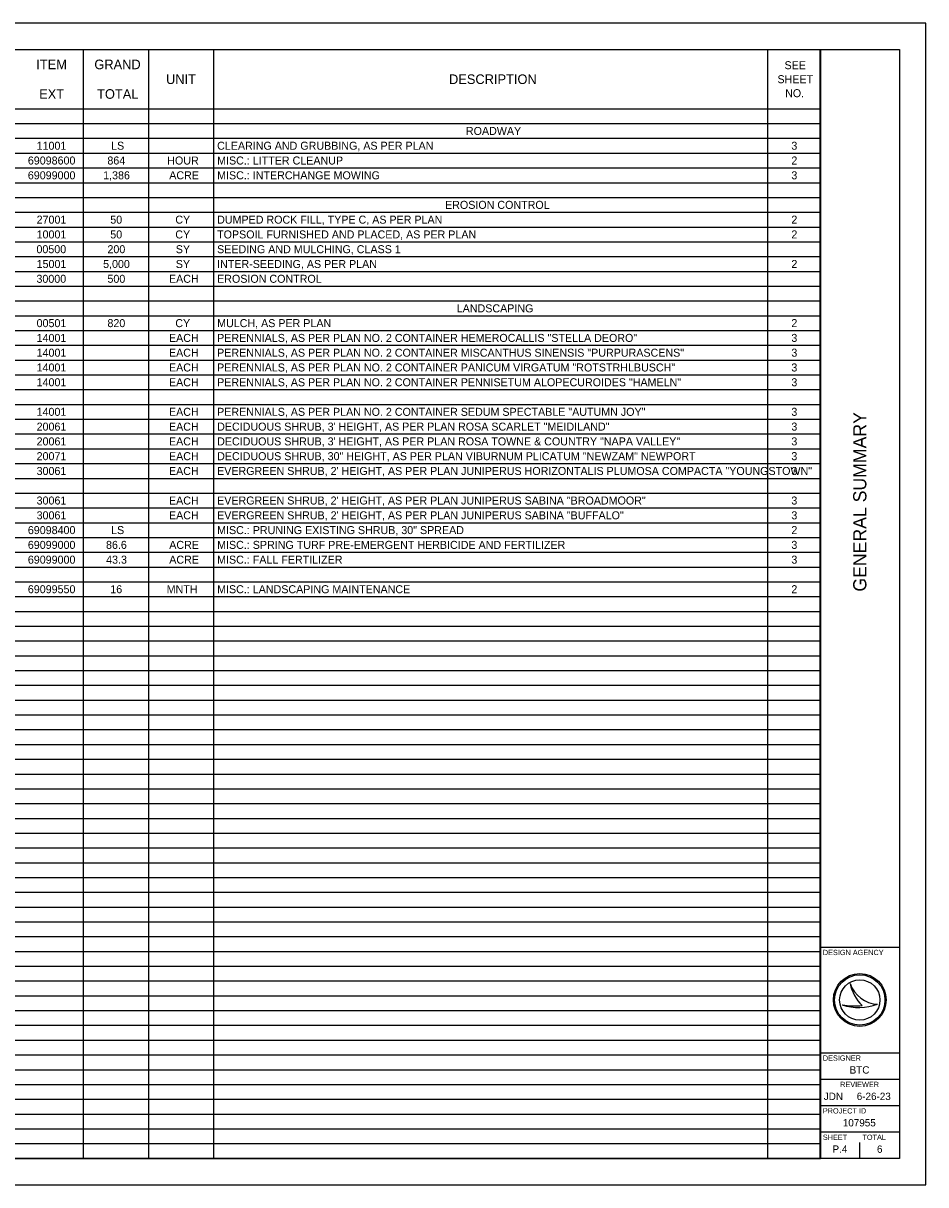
# Model space of a CAD drawing. Extents: x 0 to 34, y 0 to 22.
# Drawn here: x 16.9 to 34, y 0 to 22 of the extents above; entities that cross this region are included whole.
import ezdxf

# ---------------------------------------------------------------- set-up
doc = ezdxf.new("R2010")
doc.units = 0
for name, color, linetype in [('Default', 7, 'Continuous'), ('SH_Border', 7, 'Continuous'), ('SH_Cut_Line', 7, 'Continuous'), ('SH_Data', 7, 'Continuous')]:
    doc.layers.add(name, color=color, linetype=linetype)

msp = doc.modelspace()

# ---------------------------------------------------------------- linework, layer by layer
at = {"layer": 'Default'}
for p, q in [((1.5, 21.5), (32.004, 21.5)), ((18.036, 21.5), (18.036, 0.5)), ((19.272, 21.5), (19.272, 0.5)), ((20.507, 21.5), (20.507, 0.5)), ((30.999, 21.5), (30.999, 0.5)), ((32.004, 21.5), (32.004, 0.5)), ((1.5, 20.38), (32.004, 20.38)), ((1.5, 20.1), (32.004, 20.1)), ((1.5, 19.82), (32.004, 19.82)), ((1.5, 19.54), (32.004, 19.54)), ((1.5, 19.26), (32.004, 19.26)), ((1.5, 18.98), (32.004, 18.98)), ((1.5, 18.7), (32.004, 18.7)), ((1.5, 18.42), (32.004, 18.42)), ((1.5, 18.14), (32.004, 18.14)), ((1.5, 17.86), (32.004, 17.86)), ((1.5, 17.58), (32.004, 17.58)), ((1.5, 17.3), (32.004, 17.3)), ((1.5, 17.02), (32.004, 17.02)), ((1.5, 16.74), (32.004, 16.74)), ((1.5, 16.46), (32.004, 16.46)), ((1.5, 16.18), (32.004, 16.18)), ((1.5, 15.9), (32.004, 15.9)), ((1.5, 15.62), (32.004, 15.62)), ((1.5, 15.34), (32.004, 15.34)), ((1.5, 15.06), (32.004, 15.06)), ((1.5, 14.78), (32.004, 14.78)), ((1.5, 14.5), (32.004, 14.5)), ((1.5, 14.22), (32.004, 14.22)), ((1.5, 13.94), (32.004, 13.94)), ((1.5, 13.66), (32.004, 13.66)), ((1.5, 13.38), (32.004, 13.38)), ((1.5, 13.1), (32.004, 13.1)), ((1.5, 12.82), (32.004, 12.82)), ((1.5, 12.54), (32.004, 12.54)), ((1.5, 12.26), (32.004, 12.26)), ((1.5, 11.98), (32.004, 11.98)), ((1.5, 11.7), (32.004, 11.7)), ((1.5, 11.42), (32.004, 11.42)), ((1.5, 11.14), (32.004, 11.14)), ((1.5, 10.86), (32.004, 10.86)), ((1.5, 10.58), (32.004, 10.58)), ((1.5, 10.3), (32.004, 10.3)), ((1.5, 10.02), (32.004, 10.02)), ((1.5, 9.74), (32.004, 9.74)), ((1.5, 9.46), (32.004, 9.46)), ((1.5, 9.18), (32.004, 9.18)), ((1.5, 8.9), (32.004, 8.9)), ((1.5, 8.62), (32.004, 8.62)), ((1.5, 8.34), (32.004, 8.34)), ((1.5, 8.06), (32.004, 8.06)), ((1.5, 7.78), (32.004, 7.78)), ((1.5, 7.5), (32.004, 7.5)), ((1.5, 7.22), (32.004, 7.22)), ((1.5, 6.94), (32.004, 6.94)), ((1.5, 6.66), (32.004, 6.66)), ((1.5, 6.38), (32.004, 6.38)), ((1.5, 6.1), (32.004, 6.1)), ((1.5, 5.82), (32.004, 5.82)), ((1.5, 5.54), (32.004, 5.54)), ((1.5, 5.26), (32.004, 5.26)), ((1.5, 4.98), (32.004, 4.98)), ((1.5, 4.7), (32.004, 4.7)), ((1.5, 4.42), (32.004, 4.42)), ((1.5, 4.14), (32.004, 4.14)), ((1.5, 3.86), (32.004, 3.86)), ((1.5, 3.58), (32.004, 3.58)), ((1.5, 3.3), (32.004, 3.3)), ((1.5, 3.02), (32.004, 3.02)), ((1.5, 2.74), (32.004, 2.74)), ((1.5, 2.46), (32.004, 2.46)), ((1.5, 2.18), (32.004, 2.18)), ((1.5, 1.9), (32.004, 1.9)), ((1.5, 1.62), (32.004, 1.62)), ((1.5, 1.34), (32.004, 1.34)), ((1.5, 1.06), (32.004, 1.06)), ((1.5, 0.78), (32.004, 0.78)), ((1.5, 0.5), (32.004, 0.5))]:
    msp.add_line(p, q, dxfattribs=at)
at = {"layer": 'SH_Border'}
for p, q in [((32, 0.5), (32, 21.5)), ((32, 4.5), (33.5, 4.5)), ((32, 2.5), (33.5, 2.5)), ((32, 2), (33.5, 2)), ((32, 1.5), (33.5, 1.5)), ((32, 1), (33.5, 1))]:
    msp.add_line(p, q, dxfattribs=at)
msp.add_lwpolyline([(1.5, 21.5), (33.5, 21.5), (33.5, 0.5), (1.5, 0.5)], close=True, dxfattribs=at)
at = {"layer": 'SH_Cut_Line'}
msp.add_lwpolyline([(0, 0), (34, 0), (34, 22), (0, 22)], close=True, dxfattribs=at)
at = {"layer": 'SH_Data'}
for p, q in [((32.567, 3.81), (32.567, 3.81)), ((32.417, 3.41), (32.417, 3.41)), ((32.75, 3.5), (32.75, 3.5)), ((33.087, 3.419), (33.087, 3.419)), ((32.375, 0.675), (32.375, 0.675)), ((32.75, 0.5), (32.75, 0.8))]:
    msp.add_line(p, q, dxfattribs=at)
for radius in [0.5, 0.477, 0.477, 0.382]:
    msp.add_circle((32.75, 3.5), radius, dxfattribs=at)
for centre, radius, start, end in [((33.116, 3.998), 0.58, 198.9257, 198.9319), ((33.347, 3.97), 0.796, 191.6379, 191.6421), ((33.116, 3.998), 0.58, 198.9319, 267.1657), ((33.347, 3.97), 0.796, 191.6421, 226.0947), ((32.739, 4.37), 1.013, 251.4576, 290.0832), ((32.648, 4.654), 1.266, 259.4964, 259.4995), ((32.739, 4.37), 1.013, 251.4527, 251.4576), ((32.648, 4.654), 1.266, 259.4995, 276.6672)]:
    msp.add_arc(centre, radius, start, end, dxfattribs=at)

# ---------------------------------------------------------------- texts
at = {"layer": 'Default'}
for s, height, p in [('ITEM', 0.1818, (17.147, 21.129)), ('GRAND', 0.1818, (18.247, 21.129)), ('SEE ', 0.1515, (31.324, 21.129)), ('UNIT', 0.1818, (19.606, 20.849)), ('DESCRIPTION', 0.18184, (24.967, 20.849)), ('SHEET ', 0.1515, (31.19, 20.864)), ('EXT', 0.1818, (17.201, 20.569)), ('TOTAL', 0.1818, (18.299, 20.569)), ('NO.', 0.1515, (31.335, 20.599)), ('ROADWAY', 0.1515, (25.287, 19.884)), ('11001', 0.1515, (17.153, 19.604)), ('LS', 0.1515, (18.564, 19.604)), ('CLEARING AND GRUBBING, AS PER PLAN', 0.15153, (20.573, 19.604)), ('3', 0.152, (31.453, 19.604)), ('69098600', 0.1515, (16.987, 19.324)), ('864', 0.1515, (18.494, 19.324)), ('HOUR', 0.1515, (19.628, 19.324)), ('MISC.: LITTER CLEANUP', 0.15153, (20.573, 19.324)), ('2', 0.152, (31.453, 19.324)), ('69099000', 0.1515, (16.987, 19.044)), ('1,386', 0.1515, (18.414, 19.044)), ('ACRE', 0.1515, (19.666, 19.044)), ('MISC.: INTERCHANGE MOWING', 0.15153, (20.573, 19.044)), ('3', 0.152, (31.453, 19.044)), ('EROSION CONTROL', 0.15153, (24.892, 18.484)), ('27001', 0.1515, (17.153, 18.204)), ('50', 0.1515, (18.549, 18.204)), ('CY', 0.1515, (19.781, 18.204)), ('DUMPED ROCK FILL, TYPE C, AS PER PLAN', 0.15153, (20.573, 18.204)), ('2', 0.152, (31.453, 18.204)), ('10001', 0.1515, (17.153, 17.924)), ('50', 0.1515, (18.549, 17.924)), ('CY', 0.1515, (19.781, 17.924)), ('TOPSOIL FURNISHED AND PLACED, AS PER PLAN', 0.15153, (20.573, 17.924)), ('2', 0.152, (31.453, 17.924)), ('00500', 0.1515, (17.15, 17.644)), ('200', 0.1515, (18.495, 17.644)), ('SY', 0.1515, (19.79, 17.644)), ('SEEDING AND MULCHING, CLASS 1', 0.15153, (20.573, 17.644)), ('15001', 0.1515, (17.153, 17.364)), ('5,000', 0.1515, (18.413, 17.364)), ('SY', 0.1515, (19.79, 17.364)), ('INTER-SEEDING, AS PER PLAN', 0.15153, (20.573, 17.364)), ('2', 0.152, (31.453, 17.364)), ('30000', 0.1515, (17.15, 17.084)), ('500', 0.1515, (18.495, 17.084)), ('EACH', 0.1515, (19.661, 17.084)), ('EROSION CONTROL', 0.15153, (20.573, 17.084)), ('LANDSCAPING', 0.15153, (25.113, 16.524)), ('00501', 0.1515, (17.153, 16.244)), ('820', 0.1515, (18.495, 16.244)), ('CY', 0.1515, (19.781, 16.244)), ('MULCH, AS PER PLAN', 0.15153, (20.573, 16.244)), ('2', 0.152, (31.453, 16.244)), ('14001', 0.1515, (17.153, 15.964)), ('EACH', 0.1515, (19.661, 15.964)), ('PERENNIALS, AS PER PLAN NO. 2 CONTAINER HEMEROCALLIS "STELLA DEORO"', 0.15153, (20.573, 15.964)), ('3', 0.152, (31.453, 15.964)), ('14001', 0.1515, (17.153, 15.684)), ('EACH', 0.1515, (19.661, 15.684)), ('PERENNIALS, AS PER PLAN NO. 2 CONTAINER MISCANTHUS SINENSIS "PURPURASCENS"', 0.15153, (20.573, 15.684)), ('3', 0.152, (31.453, 15.684)), ('14001', 0.1515, (17.153, 15.404)), ('EACH', 0.1515, (19.661, 15.404)), ('PERENNIALS, AS PER PLAN NO. 2 CONTAINER PANICUM VIRGATUM "ROTSTRHLBUSCH"', 0.15153, (20.573, 15.404)), ('3', 0.152, (31.453, 15.404)), ('14001', 0.1515, (17.153, 15.124)), ('EACH', 0.1515, (19.661, 15.124)), ('PERENNIALS, AS PER PLAN NO. 2 CONTAINER PENNISETUM ALOPECUROIDES "HAMELN"', 0.15153, (20.573, 15.124)), ('3', 0.152, (31.453, 15.124)), ('14001', 0.1515, (17.153, 14.564)), ('EACH', 0.1515, (19.661, 14.564)), ('PERENNIALS, AS PER PLAN NO. 2 CONTAINER SEDUM SPECTABLE "AUTUMN JOY"', 0.15153, (20.573, 14.564)), ('3', 0.152, (31.453, 14.564)), ('20061', 0.1515, (17.153, 14.284)), ('EACH', 0.1515, (19.661, 14.284)), ('DECIDUOUS SHRUB, 3\' HEIGHT, AS PER PLAN ROSA SCARLET "MEIDILAND"', 0.15153, (20.573, 14.284)), ('3', 0.152, (31.453, 14.284)), ('20061', 0.1515, (17.153, 14.004)), ('EACH', 0.1515, (19.661, 14.004)), ('DECIDUOUS SHRUB, 3\' HEIGHT, AS PER PLAN ROSA TOWNE & COUNTRY "NAPA VALLEY"', 0.15153, (20.573, 14.004)), ('3', 0.152, (31.453, 14.004)), ('20071', 0.1515, (17.153, 13.724)), ('EACH', 0.1515, (19.661, 13.724)), ('DECIDUOUS SHRUB, 30" HEIGHT, AS PER PLAN VIBURNUM PLICATUM "NEWZAM" NEWPORT', 0.15153, (20.573, 13.724)), ('3', 0.152, (31.453, 13.724)), ('30061', 0.1515, (17.153, 13.444)), ('EACH', 0.1515, (19.661, 13.444)), ('EVERGREEN SHRUB, 2\' HEIGHT, AS PER PLAN JUNIPERUS HORIZONTALIS PLUMOSA COMPACTA "YOUNGSTOWN"', 0.15153, (20.573, 13.444)), ('3', 0.152, (31.453, 13.444)), ('30061', 0.1515, (17.153, 12.884)), ('EACH', 0.1515, (19.661, 12.884)), ('EVERGREEN SHRUB, 2\' HEIGHT, AS PER PLAN JUNIPERUS SABINA "BROADMOOR"', 0.15153, (20.573, 12.884)), ('3', 0.152, (31.453, 12.884)), ('30061', 0.1515, (17.153, 12.604)), ('EACH', 0.1515, (19.661, 12.604)), ('EVERGREEN SHRUB, 2\' HEIGHT, AS PER PLAN JUNIPERUS SABINA "BUFFALO"', 0.15153, (20.573, 12.604)), ('3', 0.152, (31.453, 12.604)), ('69098400', 0.1515, (16.987, 12.324)), ('LS', 0.1515, (18.564, 12.324)), ('MISC.: PRUNING EXISTING SHRUB, 30" SPREAD', 0.15153, (20.573, 12.324)), ('2', 0.152, (31.453, 12.324)), ('69099000', 0.1515, (16.987, 12.044)), ('86.6', 0.1515, (18.468, 12.044)), ('ACRE', 0.1515, (19.666, 12.044)), ('MISC.: SPRING TURF PRE-EMERGENT HERBICIDE AND FERTILIZER', 0.15153, (20.573, 12.044)), ('3', 0.152, (31.453, 12.044)), ('69099000', 0.1515, (16.987, 11.764)), ('43.3', 0.1515, (18.47, 11.764)), ('ACRE', 0.1515, (19.666, 11.764)), ('MISC.: FALL FERTILIZER', 0.15153, (20.573, 11.764)), ('3', 0.152, (31.453, 11.764)), ('69099550', 0.1515, (16.987, 11.204)), ('16', 0.1515, (18.549, 11.204)), ('MNTH', 0.1515, (19.618, 11.204)), ('MISC.: LANDSCAPING MAINTENANCE', 0.15153, (20.573, 11.204)), ('2', 0.152, (31.453, 11.204))]:
    msp.add_text(s, height=height, dxfattribs=at).set_placement(p)
at = {"layer": 'SH_Data'}
msp.add_text('GENERAL SUMMARY', height=0.25, rotation=90, dxfattribs=at).set_placement((32.875, 11.235))
for s, height, p in [('DESIGN AGENCY', 0.1, (32.05, 4.35)), ('DESIGNER', 0.1, (32.05, 2.35)), ('BTC', 0.14, (32.558, 2.105)), ('REVIEWER', 0.1, (32.378, 1.85)), ('JDN', 0.14, (32.068, 1.605)), ('6-26-23', 0.14, (32.692, 1.605)), ('PROJECT ID', 0.1, (32.05, 1.35)), ('107955', 0.14, (32.428, 1.105)), ('SHEET', 0.1, (32.05, 0.85)), ('TOTAL', 0.1, (32.8, 0.85)), ('P.4', 0.14, (32.233, 0.605)), ('6', 0.14, (33.075, 0.605))]:
    msp.add_text(s, height=height, dxfattribs=at).set_placement(p)

doc.saveas('drawing.dxf')
